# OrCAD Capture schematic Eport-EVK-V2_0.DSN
size Custom; title: HF-Eport EVK; rev: 1.0; note: HF-Eport EVK SCH V1.0
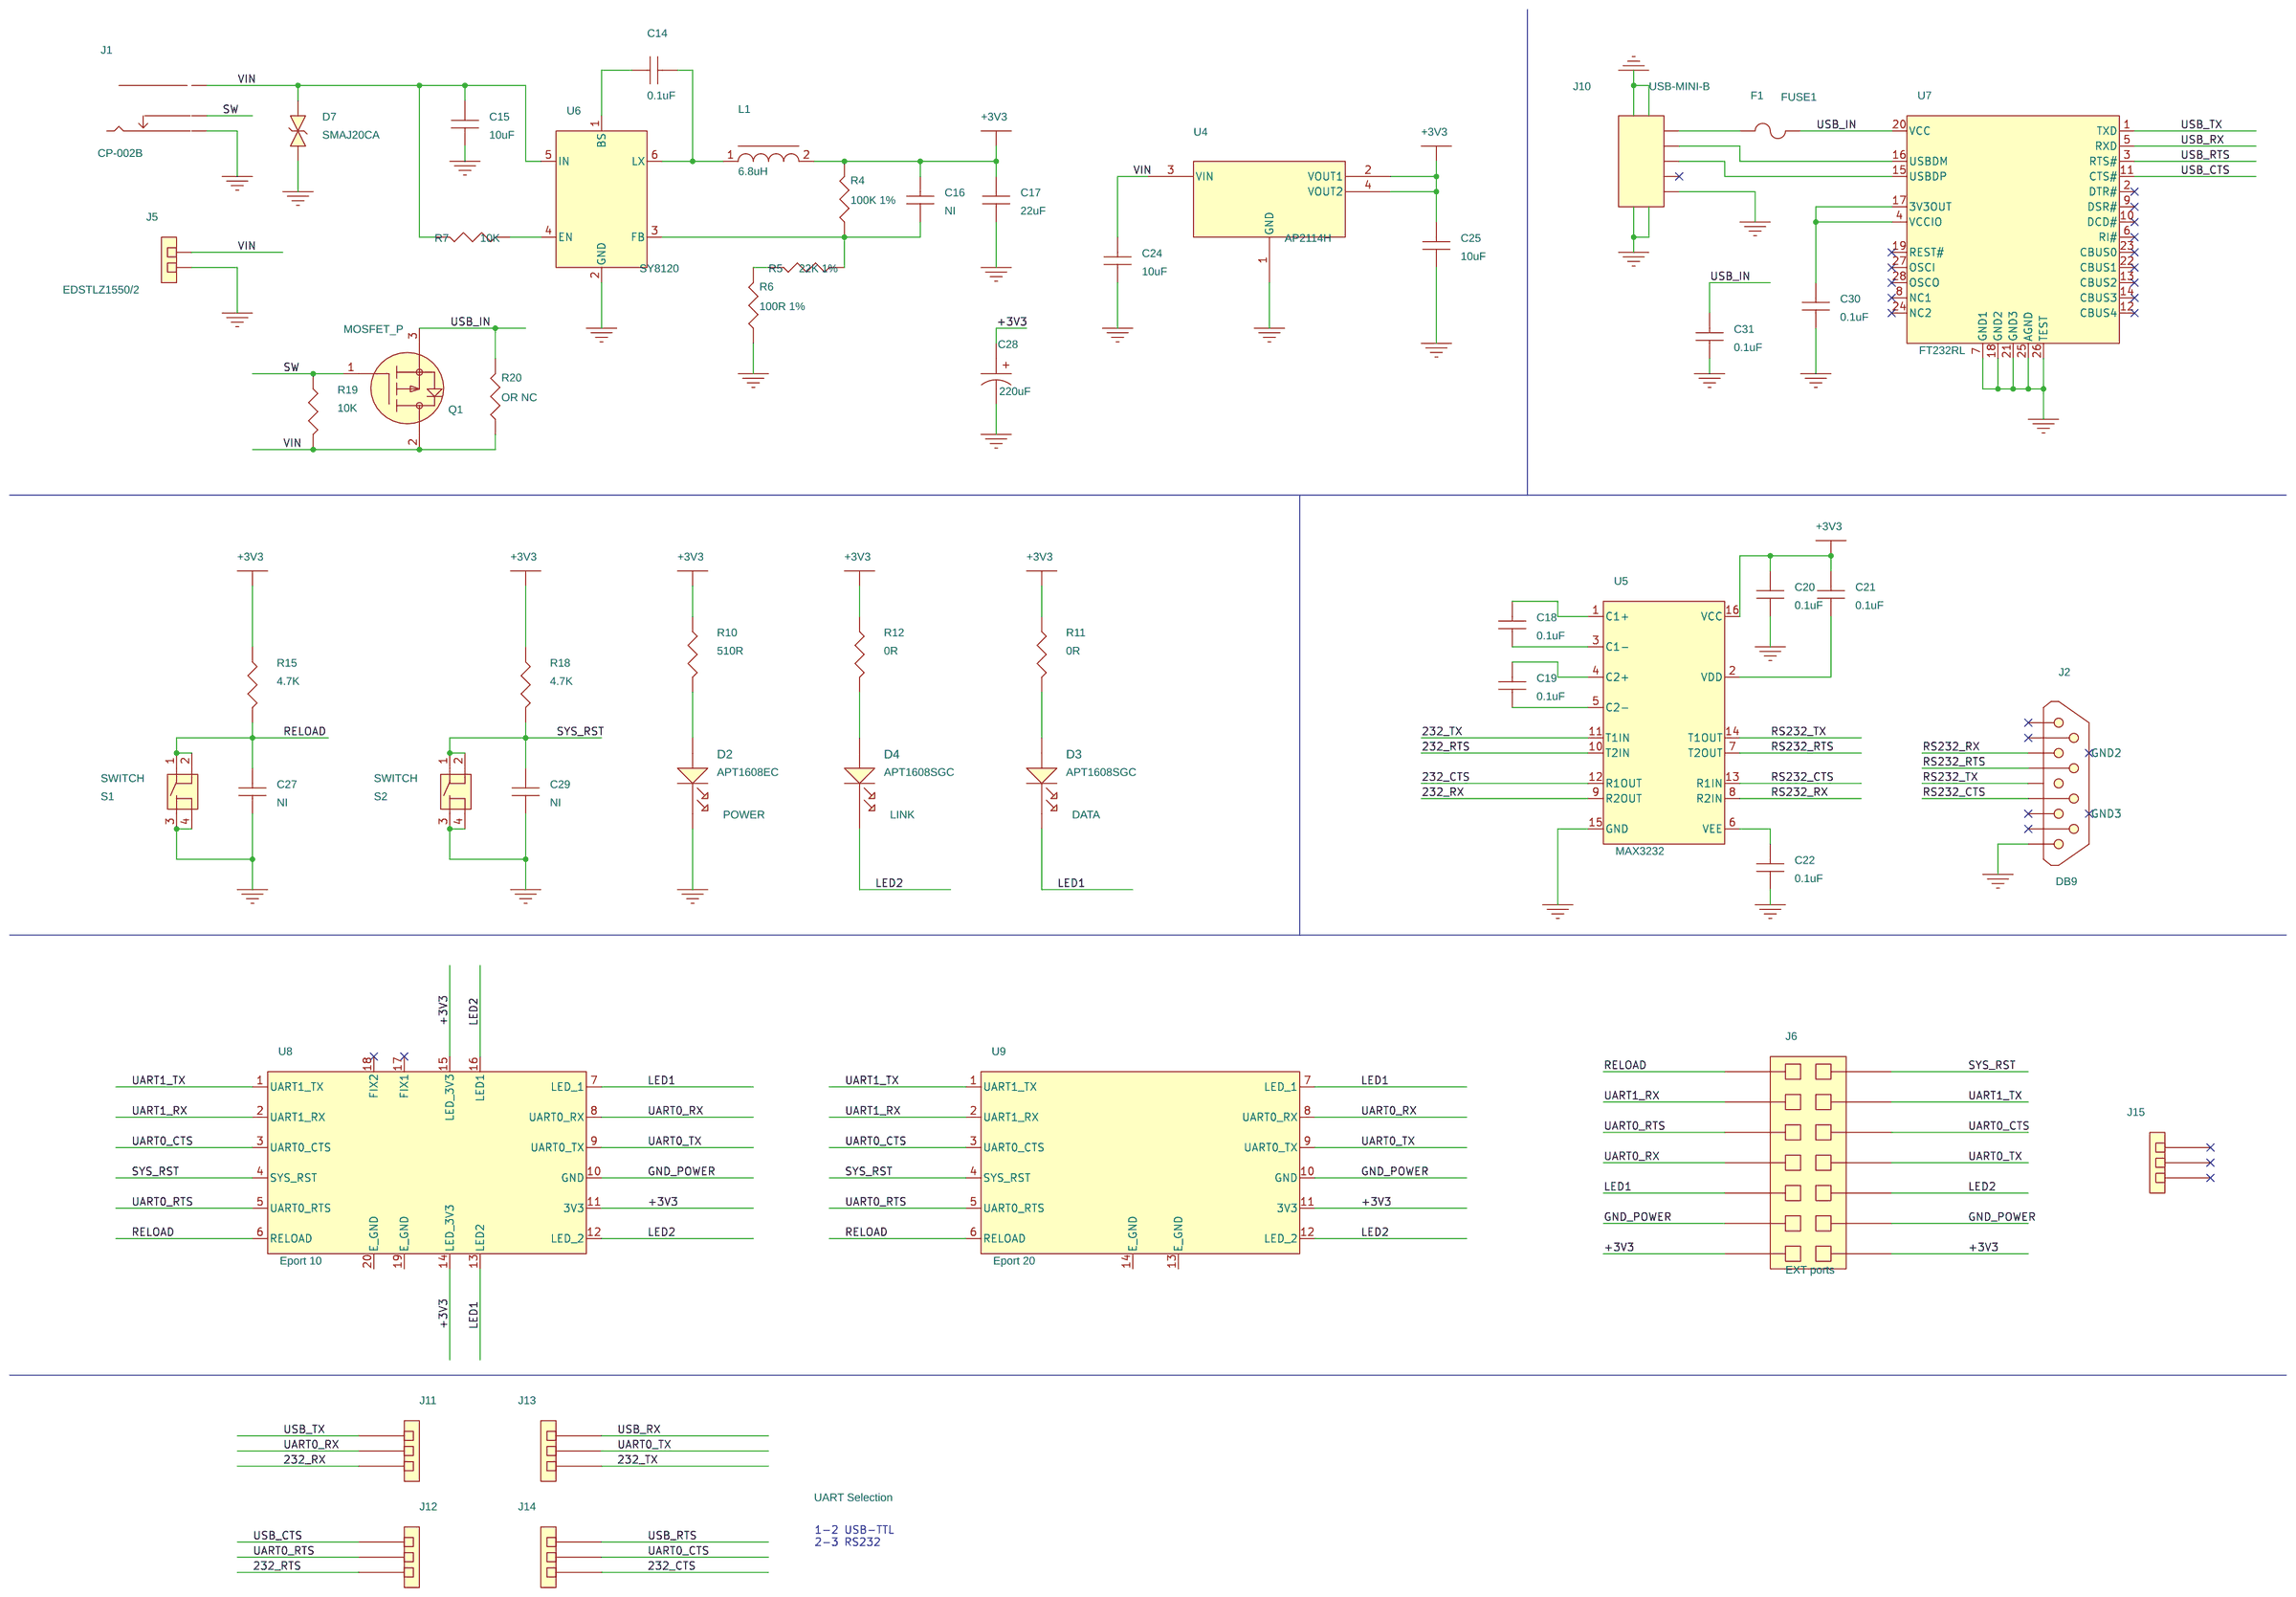
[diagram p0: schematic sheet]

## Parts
C14  0.1uF  [C0603]
C15  10uF  [C1206]
C16  NI  [C0603]
C17  22uF  [C1206]
C18  0.1uF  [C0603]
C19  0.1uF  [C0603]
C20  0.1uF  [C0603]
C21  0.1uF  [C0603]
C22  0.1uF  [C0603]
C24  10uF  [C1206]
C25  10uF  [C1206]
C27  NI  [C0603]
C28  220uF  [rad3-5]
C29  NI  [C0603]
C30  0.1uF  [C0603]
C31  0.1uF  [C0603]
D2  APT1608EC  [LED0603]
D3  APT1608SGC  [LED0603]
D4  APT1608SGC  [LED0603]
D7  SMAJ20CA  [do-214ac]
F1  FUSE1  [r0603]
J1  CP-002B  [CP-002B]
J2  DB9  [DB-9]
J5  EDSTLZ1550/2  [therm2]
J6  EXT ports  [DIP14]
J10  USB-MINI-B  [usb_mini_b]
J11  UART Selection  [sip3]
J12  nReady selection  [sip3]
J13  nReady selection  [sip3]
J14  nReady selection  [sip3]
J15  nReady selection  [sip_3]
L1  6.8uH  [L3012]
Q1  MOSFET_P  [sot-23]
R4  100K 1%  [R0603]
R5  22K 1%  [R0603]
R6  100R 1%  [R0603]
R7  10K  [R0603]
R10  510R  [R0603]
R11  0R  [R0603]
R12  0R  [R0603]
R15  4.7K  [R0603]
R18  4.7K  [R0603]
R19  10K  [R0603]
R20  OR NC  [R0603]
S1  SWITCH  [sw-4]
S2  SWITCH  [sw-4]
U4  AP2114H  [SOT223]
U5  MAX3232  [SOIC-G16]
U6  SY8120  [SOT23-6]
U7  FT232RL  [ssop-28]
U8  Eport 10  [eport]
U9  Eport 20  [ep20]

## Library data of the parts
C14 = C0603: CAP CER 0.1UF 16V X7R 10% 0603; DNI OPT: DNI; PN: CC0603KRX7R7BB104; Vendor: YAGEO
C15 = C0603: CAP CER 10UF 25V X7R 1206; DNI OPT: DNI; PN: C3216X7R1E106M160AB; Vendor: TDK
C16 = C0603: DNI OPT: DNI
C17 = C0603: CAP CER 22UF 25V X5R 1206; DNI OPT: DNI; PN: C3216X5R1E226M160AB; Vendor: TDK
C18-C22 C27 C29-C31 = C0603: CAP CER 0.1UF 16V X7R 10% 0603; PN: CC0603KRX7R7BB104; Vendor: YAGEO
C24 C25 = C0603: CAP CER 10UF 25V X7R 1206; PN: C3216X7R1E106M160AB; Vendor: TDK
C28 = CAP_POL_0: CAP ALUM 220UF 20% 25V RADIAL; PN: EEU-FC1E221; Vendor: PANASONIC
D2 = LED: LED RED CLEAR 0603 SMD; Author: 0; DNI: POWER; Digi-Key #: 754-1434-1-ND; Full reel Digi-Key #: 754-1434-1-ND; Vendor: Kingbright
D3 = LED: LED GREEN CLEAR 0603 SMD; Author: 0; Color: Green; DNI: DATA; Vendor: Kingbright
D4 = LED: LED GREEN CLEAR 0603 SMD; Author: 0; Color: Green; DNI: LINK; Vendor: Kingbright
D7 = SMAJ20A: TVS DIODE 20VWM 32.4VC SMA; DNI OPT: DNI; Vendor: Littelfuse Inc.
F1 = FUSE1
J1 = CP-002B: CONN PWR JACK 2.5X5.5MM HIGH CUR; PN: PJ-002BH; Vendor: CUI
J2 = RS232_0: CONN D-SUB PLUG 9POS R/A SOLDER; PN: 182-009-113R561; Vendor: Norcomp Inc.
J5 = SIP2: TERM BLOCK HDR 2POS R/A 3.81MM; DNI OPT: DNI; Vendor: On Shore Technology Inc
J6 = ?_0: CONN HEADER VERT .100 14POS 15AU; PN: 87227-7; Vendor: TE
J10 = USB-MINI-B_0
J11-J15 = HDR5X1_0: CONN HEADER VERT .100 3POS 15AU; PN: 87224-3; Vendor: TE
L1 = INDUCTOR: FIXED IND 6.8UH 1.6A 0.3 OHM; DNI OPT: DNI; PN: WPN3012H6R8MT; Vendor: SUNLOAD
Q1 = MOSFET_P_0
R4 = R_10_K_0402: RES SMD 100K OHM 1% 1/10W 0603; DNI OPT: DNI; PN: RC0603FR-07100KL; Vendor: YAGEO
R5 = R_10_K_0402: RES SMD 22K OHM 1% 1/10W 0603; DNI OPT: DNI; PN: AC0603FR-0722KL; Vendor: YAGEO
R6 R20 = R_10_K_0402: RES SMD 100 OHM 1% 1/10W 0603; DNI OPT: DNI; PN: RC0603FR-07100RL; Vendor: YAGEO
R7 R19 = R_10_K_0402: RES SMD 10K OHM 5% 1/10W 0603; DNI OPT: DNI; PN: RC0603JR-0710KL; Vendor: YAGEO
R10-R12 = R_10_K_0402: RES SMD 510 OHM 5% 1/10W 0603; PN: RC0603JR-07510RL; Vendor: YAGEO
R15 R18 = R_10_K_0402: RES SMD 4.7K OHM 5% 1/10W 0603; PN: RC0603JR-074K7L; Vendor: YAGEO
S1 S2 = SWITCH_2: SWITCH TACTILE SPST-NO 50MA 12V 4.5*4.5MM; PN: TL3305AF260QG; Vendor: E-Switch
U4 = TLV1117-33: IC REG LDO 3.3V 1A SOT223; Author: Emil S.; DIGI-KEY: 296-21108-1-ND; PN: AP2114H-3.3TRG1; Vendor: Diodes Incorporated
U5 = MAX3232_0: IC RS232 3V5.5V 15KVESD 16-SSOP; PN: MAX3232ECDWR; Vendor: TI
U6 = SY8120: IC REG BUCK ADJ 2A SOT23-6; DNI OPT: DNI; PN: SY8120B1ABC; Vendor: SILERGY
U7 = FT232RL
U8 = Eport_4
U9 = Eport_5

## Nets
+3V3: C16.2 C17.2 C20.2 C21.2 C25.2 C28.1 J6.13 J6.14 L1.2 R4.2 R10.1 R11.1 R12.1 R15.1 R18.1 U4.2(VOUT1) U4.4(VOUT2) U5.16(VCC) U8.11(3V3) U8.14(LED_3V3) U8.15(LED_3V3) U9.11(3V3)
GND_POWER: C15.1 C17.1 C20.1 C22.1 C24.1 C25.1 C27.1 C28.2 C29.1 C30.1 C31.1 D2.2 D7.1 J1.2 J2.5 J5.2 J6.11 J6.12 J10.5 J10.6 J10.7 J10.8 J10.9 R6.1 S1.3 S1.4 S2.3 S2.4 U4.1(GND) U5.15(GND) U6.2(GND) U7.7(GND1) U7.18(GND2) U7.21(GND3) U7.25(AGND) U7.26(TEST) U8.10(GND) U9.10(GND)
VIN: C15.2 C24.2 D7.2 J1.1 J5.1 Q1.2(S) R7.2 R19.2 R20.1 U4.3(VIN) U6.5(IN)
232_CTS: J14.3 U5.12(R1OUT)
232_RTS: J12.3 U5.10(T2IN)
232_RX: J11.3 U5.9(R2OUT)
232_TX: J13.3 U5.11(T1IN)
E_GND: U8.19(E_GND) U8.20(E_GND) U9.13(E_GND) U9.14(E_GND)
LED1: D3.2 J6.10 U8.7(LED_1) U8.13(LED2) U9.7(LED_1)
LED2: D4.2 J6.9 U8.12(LED_2) U8.16(LED1) U9.12(LED_2)
RELOAD: C27.2 J6.2 R15.2 S1.1 S1.2 U8.6(RELOAD) U9.6(RELOAD)
RS232_CTS: J2.8 U5.13(R1IN)
RS232_RTS: J2.7 U5.7(T2OUT)
RS232_RX: J2.2 U5.8(R2IN)
RS232_TX: J2.3 U5.14(T1OUT)
SW: J1.3 Q1.1(G) R19.1
SYS_RST: C29.2 J6.1 R18.2 S2.1 S2.2 U8.4(SYS_RST) U9.4(SYS_RST)
UART0_CTS: J6.5 J14.2 U8.3(UART0_CTS) U9.3(UART0_CTS)
UART0_RTS: J6.6 J12.2 U8.5(UART0_RTS) U9.5(UART0_RTS)
UART0_RX: J6.8 J11.2 U8.8(UART0_RX) U9.8(UART0_RX)
UART0_TX: J6.7 J13.2 U8.9(UART0_TX) U9.9(UART0_TX)
UART1_RX: J6.4 U8.2(UART1_RX) U9.2(UART1_RX)
UART1_TX: J6.3 U8.1(UART1_TX) U9.1(UART1_TX)
USB_CTS: J12.1 U7.11(CTS#)
USB_IN: C31.2 F1.2 Q1.3(D) R20.2 U7.20(VCC)
USB_RTS: J14.1 U7.3(RTS#)
USB_RX: J13.1 U7.5(RXD)
USB_TX: J11.1 U7.1(TXD)
N00175: C14.1 U6.1(BS)
N00182: C14.2 L1.1 U6.6(LX)
N00203: C16.1 R4.1 R5.1 U6.3(FB)
N00338: R7.1 U6.4(EN)
N01191: C19.1 U5.5(C2-)
N01195: C19.2 U5.4(C2+)
N01202: C18.2 U5.1(C1+)
N01209: C18.1 U5.3(C1-)
N01519: C21.1 U5.2(VDD)
N01837: C22.2 U5.6(VEE)
N15326682: D2.1 R10.2
N15326750: D3.1 R11.2
N15326833: D4.1 R12.2
N15332885: R5.2 R6.2
N15375121: F1.1 J10.1
N15375170: J10.2 U7.16(USBDM)
N15375190: J10.3 U7.15(USBDP)
N15376984: C30.2 U7.4(VCCIO) U7.17(3V3OUT)

Not connected (* = marked no-connect by the designer): J2 1* 4* 6* 9* 10(GND2)* 11(GND3)*; J10 4*; J15 1* 2* 3*; U7 2(DTR#)* 6(RI#)* 8(NC1)* 9(DSR#)* 10(DCD#)* 12(CBUS4)* 13(CBUS2)* 14(CBUS3)* 19(REST#)* 22(CBUS1)* 23(CBUS0)* 24(NC2)* 27(OSCI)* 28(OSCO)*; U8 17(FIX1)* 18(FIX2)*

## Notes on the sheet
- 1-2 USB-TTL
  2-3 RS232
